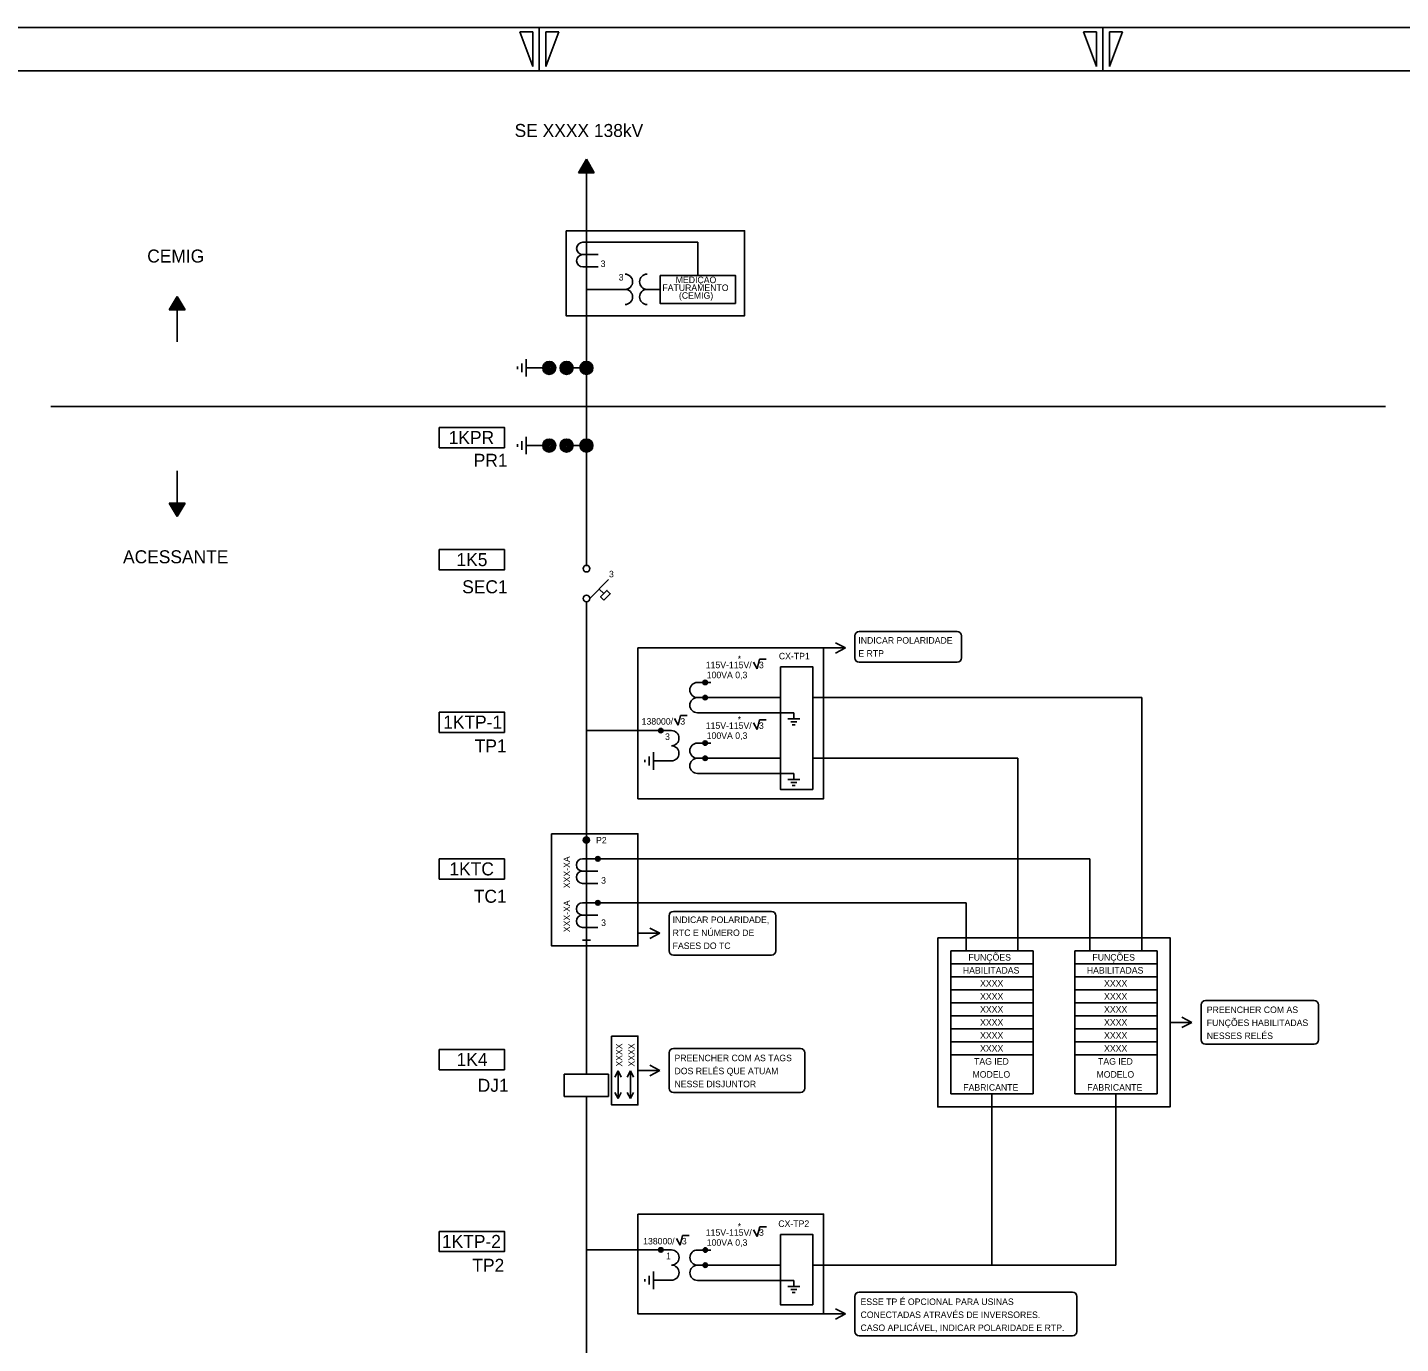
# Model space of a CAD drawing. Extents: x 563 to 1404, y 358 to 952.
# Drawn here: x 785.5 to 1102.2, y 648.4 to 952 of the extents above; entities that cross this region are included whole.
import ezdxf

# ---------------------------------------------------------------- set-up
doc = ezdxf.new("R2010")
doc.units = 0
doc.layers.add('New Level (0)', color=7, linetype='Continuous')

# ---------------------------------------------------------------- blocks, each defined once
blk = doc.blocks.new('_U3')
for p, q in [((-1.47, 0.42), (-0.62, -1.12)), ((-0.62, -1.12), (-0.07, 1.12)), ((-0.07, 1.12), (1.47, 1.12))]:
    blk.add_line(p, q)

msp = doc.modelspace()

# ---------------------------------------------------------------- linework, layer by layer
for p, q in [((914.46, 921.55), (912.65, 918.45)), ((914.46, 921.34), (912.83, 918.55)), ((912.83, 918.55), (916.08, 918.55)), ((914.46, 921.14), (913.01, 918.66)), ((913.01, 918.66), (915.9, 918.66)), ((914.46, 920.93), (913.19, 918.76)), ((913.19, 918.76), (915.72, 918.76)), ((914.46, 920.72), (913.37, 918.86)), ((913.37, 918.86), (915.54, 918.86)), ((914.46, 920.52), (913.55, 918.97)), ((913.55, 918.97), (915.36, 918.97)), ((914.46, 920.31), (913.73, 919.07)), ((913.73, 919.07), (915.18, 919.07)), ((914.46, 920.1), (913.91, 919.17)), ((913.91, 919.17), (915, 919.17)), ((914.46, 919.9), (914.09, 919.28)), ((914.09, 919.28), (914.82, 919.28)), ((914.46, 919.69), (914.27, 919.38)), ((914.27, 919.38), (914.64, 919.38)), ((916.27, 918.45), (914.46, 921.55)), ((916.08, 918.55), (914.46, 921.34)), ((915.9, 918.66), (914.46, 921.14)), ((915.72, 918.76), (914.46, 920.93)), ((915.54, 918.86), (914.46, 920.72)), ((915.36, 918.97), (914.46, 920.52)), ((915.18, 919.07), (914.46, 920.31)), ((915, 919.17), (914.46, 920.1)), ((914.82, 919.28), (914.46, 919.9)), ((914.64, 919.38), (914.46, 919.69)), ((912.65, 918.45), (916.27, 918.45)), ((912.65, 918.45), (916.27, 918.45)), ((914.46, 827.91), (914.46, 918.45)), ((913.61, 902.41), (917.15, 902.41)), ((913.61, 899.58), (917.15, 899.58)), ((917.15, 902.41), (940.14, 902.41)), ((913.61, 896.75), (917.15, 896.75)), ((914.52, 891.56), (923.36, 891.56)), ((928.46, 891.56), (931.46, 891.56)), ((820.05, 889.94), (818.24, 886.84)), ((820.05, 889.73), (818.42, 886.94)), ((818.42, 886.94), (821.67, 886.94)), ((820.05, 889.53), (818.6, 887.05)), ((818.6, 887.05), (821.49, 887.05)), ((820.05, 889.32), (818.78, 887.15)), ((818.78, 887.15), (821.31, 887.15)), ((820.05, 889.11), (818.96, 887.25)), ((818.96, 887.25), (821.13, 887.25)), ((820.05, 888.91), (819.14, 887.36)), ((819.14, 887.36), (820.95, 887.36)), ((820.05, 888.7), (819.32, 887.46)), ((819.32, 887.46), (820.77, 887.46)), ((820.05, 888.49), (819.5, 887.56)), ((819.5, 887.56), (820.59, 887.56)), ((820.05, 888.29), (819.68, 887.67)), ((819.68, 887.67), (820.41, 887.67)), ((820.05, 888.08), (819.86, 887.77)), ((819.86, 887.77), (820.23, 887.77)), ((821.86, 886.84), (820.05, 889.94)), ((821.67, 886.94), (820.05, 889.73)), ((821.49, 887.05), (820.05, 889.53)), ((821.31, 887.15), (820.05, 889.32)), ((821.13, 887.25), (820.05, 889.11)), ((820.95, 887.36), (820.05, 888.91)), ((820.77, 887.46), (820.05, 888.7)), ((820.59, 887.56), (820.05, 888.49)), ((820.41, 887.67), (820.05, 888.29)), ((820.23, 887.77), (820.05, 888.08)), ((818.24, 886.84), (821.86, 886.84)), ((818.24, 886.84), (821.86, 886.84)), ((820.05, 879.42), (820.05, 886.84)), ((899.55, 874.43), (899.55, 872.43)), ((900.55, 871.43), (900.55, 875.43)), ((898.55, 873.73), (898.55, 873.13)), ((898.55, 873.43), (898.55, 873.43)), ((901.87, 873.43), (900.55, 873.43)), ((905.87, 873.43), (901.87, 873.43)), ((914.46, 873.43), (909.87, 873.43)), ((1098.74, 864.56), (790.91, 864.56)), ((898.55, 855.83), (898.55, 855.23)), ((898.55, 855.53), (898.55, 855.53)), ((899.55, 856.53), (899.55, 854.53)), ((900.55, 853.53), (900.55, 857.53)), ((901.87, 855.53), (900.55, 855.53)), ((905.87, 855.53), (901.87, 855.53)), ((914.46, 855.53), (909.87, 855.53)), ((820.05, 849.69), (820.05, 842.28)), ((821.86, 842.28), (818.24, 842.28)), ((818.24, 842.28), (820.05, 839.18)), ((821.86, 842.28), (818.24, 842.28)), ((821.67, 842.18), (818.42, 842.18)), ((818.42, 842.18), (820.05, 839.39)), ((821.49, 842.07), (818.6, 842.07)), ((818.6, 842.07), (820.05, 839.59)), ((821.31, 841.97), (818.78, 841.97)), ((818.78, 841.97), (820.05, 839.8)), ((821.13, 841.87), (818.96, 841.87)), ((818.96, 841.87), (820.05, 840.01)), ((820.95, 841.76), (819.14, 841.76)), ((819.14, 841.76), (820.05, 840.21)), ((820.77, 841.66), (819.32, 841.66)), ((819.32, 841.66), (820.05, 840.42)), ((820.59, 841.56), (819.5, 841.56)), ((819.5, 841.56), (820.05, 840.63)), ((820.41, 841.45), (819.68, 841.45)), ((819.68, 841.45), (820.05, 840.83)), ((820.23, 841.35), (819.86, 841.35)), ((819.86, 841.35), (820.05, 841.04)), ((820.05, 839.18), (821.86, 842.28)), ((820.05, 839.39), (821.67, 842.18)), ((820.05, 839.59), (821.49, 842.07)), ((820.05, 839.8), (821.31, 841.97)), ((820.05, 840.01), (821.13, 841.87)), ((820.05, 840.21), (820.95, 841.76)), ((820.05, 840.42), (820.77, 841.66)), ((820.05, 840.63), (820.59, 841.56)), ((820.05, 840.83), (820.41, 841.45)), ((820.05, 841.04), (820.23, 841.35)), ((919.56, 824.61), (915.22, 820.27)), ((918.45, 821.38), (917.39, 822.44)), ((914.46, 819.5), (914.46, 710.55)), ((940.05, 800.9), (943.16, 800.9)), ((940.05, 797.4), (959.19, 797.4)), ((966.67, 797.4), (1042.59, 797.4)), ((1042.59, 797.4), (1042.59, 739)), ((940.05, 793.9), (962.28, 793.9)), ((963.68, 792.5), (960.88, 792.5)), ((962.28, 793.9), (962.28, 792.5)), ((914.46, 789.8), (934.05, 789.8)), ((961.58, 791.8), (962.98, 791.8)), ((961.94, 791.1), (962.62, 791.1)), ((940.05, 786.91), (943.16, 786.91)), ((927.92, 783.04), (927.92, 782.5)), ((928.93, 781.78), (928.93, 783.82)), ((929.96, 784.85), (929.96, 780.75)), ((934.05, 782.8), (929.96, 782.8)), ((940.05, 783.41), (943.16, 783.41)), ((940.05, 783.41), (959.19, 783.41)), ((966.67, 783.41), (1013.99, 783.41)), ((1013.99, 783.41), (1013.99, 739)), ((940.05, 779.91), (962.28, 779.91)), ((962.28, 779.91), (962.28, 778.51)), ((963.68, 778.51), (960.88, 778.51)), ((961.58, 777.81), (962.98, 777.81)), ((961.94, 777.11), (962.62, 777.11)), ((913.55, 760.21), (1030.61, 760.21)), ((1030.61, 760.21), (1030.61, 739)), ((913.55, 757.38), (917.09, 757.38)), ((913.55, 754.55), (917.09, 754.55)), ((913.55, 750.07), (1002.01, 750.07)), ((1002.01, 750.07), (1002.01, 739)), ((913.55, 747.24), (917.09, 747.24)), ((913.55, 744.41), (917.09, 744.41)), ((1017.49, 739), (998.51, 739)), ((998.51, 739), (998.51, 706)), ((1017.49, 739), (1017.49, 706)), ((1046.09, 739), (1027.11, 739)), ((1027.11, 739), (1027.11, 706)), ((1046.09, 739), (1046.09, 706)), ((1017.49, 736), (998.51, 736)), ((1046.09, 736), (1027.11, 736)), ((1017.49, 733), (998.51, 733)), ((1046.09, 733), (1027.11, 733)), ((1017.49, 730), (998.51, 730)), ((1046.09, 730), (1027.11, 730)), ((1017.49, 727), (998.51, 727)), ((1046.09, 727), (1027.11, 727)), ((1017.49, 724), (998.51, 724)), ((1046.09, 724), (1027.11, 724)), ((1017.49, 721), (998.51, 721)), ((1017.49, 721), (998.51, 721)), ((1046.09, 721), (1027.11, 721)), ((1046.09, 721), (1027.11, 721)), ((1017.49, 718), (998.51, 718)), ((1046.09, 718), (1027.11, 718)), ((1017.49, 715), (998.51, 715)), ((1046.09, 715), (1027.11, 715)), ((909.34, 705.43), (909.34, 710.55)), ((909.34, 710.55), (919.58, 710.55)), ((919.58, 710.55), (919.58, 705.43)), ((921.74, 711.3), (921.03, 709.89)), ((921.74, 704.93), (921.74, 711.3)), ((921.74, 711.3), (922.44, 709.89)), ((924.59, 711.3), (923.88, 709.89)), ((924.59, 704.93), (924.59, 711.3)), ((924.59, 711.3), (925.29, 709.89)), ((921.74, 704.93), (921.03, 706.35)), ((921.74, 704.93), (922.44, 706.35)), ((924.59, 704.93), (923.88, 706.35)), ((924.59, 704.93), (925.29, 706.35)), ((919.58, 705.43), (909.34, 705.43)), ((914.46, 705.43), (914.46, 637.7)), ((1017.49, 706), (998.51, 706)), ((1008, 706), (1008, 666.5)), ((1046.09, 706), (1027.11, 706)), ((1036.6, 706), (1036.6, 666.5)), ((914.46, 670.03), (934.06, 670.03)), ((940.06, 670), (943.17, 670)), ((940.06, 666.5), (959.19, 666.5)), ((966.67, 666.5), (1036.6, 666.5)), ((927.93, 663.27), (927.93, 662.73)), ((928.94, 662.01), (928.94, 664.05)), ((929.96, 665.08), (929.96, 660.98)), ((934.06, 663.03), (929.96, 663.03)), ((940.06, 663), (962.29, 663)), ((962.29, 663), (962.29, 661.6)), ((963.69, 661.6), (960.89, 661.6)), ((961.59, 660.9), (962.99, 660.9)), ((961.94, 660.2), (962.63, 660.2))]:
    msp.add_line(p, q)
msp.add_lwpolyline([(918.48, 819.88), (917.72, 820.64), (919.19, 822.12), (919.96, 821.35)], close=True)
for centre, radius in [((905.87, 873.43), 1.5), ((905.87, 873.43), 1.25), ((905.87, 873.43), 1), ((905.87, 873.43), 0.75), ((909.87, 873.43), 1.5), ((909.87, 873.43), 1.25), ((909.87, 873.43), 1), ((909.87, 873.43), 0.75), ((914.46, 873.43), 1.5), ((914.46, 873.43), 1.25), ((914.46, 873.43), 1), ((914.46, 873.43), 0.75), ((905.87, 873.43), 0.5), ((905.87, 873.43), 0.25), ((909.87, 873.43), 0.5), ((909.87, 873.43), 0.25), ((914.46, 873.43), 0.5), ((914.46, 873.43), 0.25), ((905.87, 855.53), 1.5), ((905.87, 855.53), 1.25), ((905.87, 855.53), 1), ((905.87, 855.53), 0.75), ((905.87, 855.53), 0.5), ((905.87, 855.53), 0.25), ((909.87, 855.53), 1.5), ((909.87, 855.53), 1.25), ((909.87, 855.53), 1), ((909.87, 855.53), 0.75), ((909.87, 855.53), 0.5), ((909.87, 855.53), 0.25), ((914.46, 855.53), 1.5), ((914.46, 855.53), 1.25), ((914.46, 855.53), 1), ((914.46, 855.53), 0.75), ((914.46, 855.53), 0.5), ((914.46, 855.53), 0.25), ((914.46, 827.14), 0.768), ((914.46, 820.27), 0.768), ((941.85, 800.9), 0.511), ((941.85, 800.9), 0.288), ((941.85, 797.4), 0.511), ((941.85, 797.4), 0.288), ((931.61, 789.8), 0.511), ((931.61, 789.8), 0.288), ((941.85, 786.91), 0.511), ((941.85, 786.91), 0.288), ((941.85, 783.41), 0.511), ((941.85, 783.41), 0.288), ((914.45, 764.55), 0.729), ((914.46, 764.54), 0.511), ((914.46, 764.54), 0.288), ((917.09, 760.21), 0.511), ((917.09, 760.21), 0.288), ((917.09, 750.07), 0.511), ((917.09, 750.07), 0.288), ((931.62, 670.03), 0.511), ((931.62, 670.03), 0.288), ((941.86, 670), 0.511), ((941.86, 670), 0.288), ((941.86, 666.5), 0.511), ((941.86, 666.5), 0.288)]:
    msp.add_circle(centre, radius)
for centre, radius, start, end in [((913.61, 900.99), 1.42, 90, 270), ((913.61, 898.16), 1.42, 90, 270), ((923.36, 893.31), 1.75, 270, 90), ((928.46, 893.31), 1.75, 90, 270), ((923.36, 889.81), 1.75, 270, 90), ((928.46, 889.81), 1.75, 90, 270), ((940.05, 799.15), 1.75, 90, 270), ((940.05, 795.65), 1.75, 90, 270), ((934.05, 788.05), 1.75, 270, 90), ((934.05, 784.55), 1.75, 270, 90), ((940.05, 785.16), 1.75, 90, 270), ((940.05, 781.66), 1.75, 90, 270), ((913.55, 758.8), 1.42, 90, 270), ((913.55, 755.97), 1.42, 90, 270), ((913.55, 748.66), 1.42, 90, 270), ((913.55, 745.83), 1.42, 90, 270), ((934.06, 668.28), 1.75, 270, 90), ((940.06, 668.25), 1.75, 90, 270), ((934.06, 664.78), 1.75, 270, 90), ((940.06, 664.75), 1.75, 90, 270)]:
    msp.add_arc(centre, radius, start, end)
at = {"layer": 'New Level (0)'}
for p, q in [((1403.58, 951.96), (562.58, 951.96)), ((1403.58, 951.96), (562.58, 951.96)), ((902.08, 950.96), (899.08, 950.96)), ((899.08, 950.96), (902.08, 942.96)), ((902.08, 942.96), (902.08, 950.96)), ((903.58, 951.96), (903.58, 941.96)), ((905.08, 942.96), (905.08, 950.96)), ((905.08, 950.96), (908.08, 950.96)), ((908.08, 950.96), (905.08, 942.96)), ((1032.08, 950.96), (1029.08, 950.96)), ((1029.08, 950.96), (1032.08, 942.96)), ((1032.08, 942.96), (1032.08, 950.96)), ((1033.58, 951.96), (1033.58, 941.96)), ((1035.08, 942.96), (1035.08, 950.96)), ((1035.08, 950.96), (1038.08, 950.96)), ((1038.08, 950.96), (1035.08, 942.96)), ((1393.58, 941.96), (572.58, 941.96)), ((940.14, 894.79), (940.14, 902.41)), ((976.35, 806.55), (976.35, 811.62)), ((977.35, 812.62), (984.7, 812.62)), ((984.7, 812.62), (999.96, 812.62)), ((1000.96, 811.62), (1000.96, 806.55)), ((969.16, 808.86), (974.19, 808.86)), ((974.19, 808.86), (971.89, 810.07)), ((974.19, 808.86), (971.89, 807.65)), ((999.96, 805.55), (977.35, 805.55)), ((934.51, 748.1), (941.86, 748.1)), ((941.86, 748.1), (957.12, 748.1)), ((933.51, 738.99), (933.51, 747.1)), ((958.12, 747.1), (958.12, 738.99)), ((913.56, 741.46), (915.36, 741.46)), ((926.32, 743.04), (931.35, 743.04)), ((931.35, 743.04), (929.05, 744.25)), ((931.35, 743.04), (929.05, 741.83)), ((957.12, 737.99), (934.51, 737.99)), ((1056.28, 718.45), (1056.28, 726.56)), ((1057.28, 727.56), (1064.63, 727.56)), ((1064.63, 727.56), (1082.29, 727.56)), ((1083.29, 726.56), (1083.29, 718.45)), ((1049.09, 722.5), (1054.12, 722.5)), ((1054.12, 722.5), (1051.83, 723.71)), ((1054.12, 722.5), (1051.83, 721.3)), ((934.51, 716.45), (941.86, 716.45)), ((941.86, 716.45), (963.8, 716.45)), ((1082.29, 717.45), (1057.28, 717.45)), ((933.51, 707.33), (933.51, 715.45)), ((964.8, 715.45), (964.8, 707.33)), ((926.32, 711.39), (931.35, 711.39)), ((931.35, 711.39), (929.05, 712.6)), ((931.35, 711.39), (929.05, 710.18)), ((963.8, 706.33), (934.51, 706.33)), ((976.35, 651.19), (976.35, 659.31)), ((977.35, 660.31), (984.71, 660.31)), ((984.71, 660.31), (1026.54, 660.31)), ((1027.54, 659.31), (1027.54, 651.19)), ((974.2, 655.25), (971.9, 656.46)), ((969.17, 655.25), (974.2, 655.25)), ((974.2, 655.25), (971.9, 654.04)), ((1026.54, 650.19), (977.35, 650.19))]:
    msp.add_line(p, q, dxfattribs=at)
for points in [[(909.78, 905.07), (950.94, 905.07), (950.94, 885.46), (909.78, 885.46)], [(931.46, 894.79), (948.81, 894.79), (948.81, 888.32), (931.46, 888.32)], [(880.5, 859.7), (895.52, 859.7), (895.52, 855.02), (880.5, 855.02)], [(880.5, 831.54), (895.52, 831.54), (895.52, 826.86), (880.5, 826.86)], [(926.32, 808.86), (969.16, 808.86), (969.16, 774.07), (926.32, 774.07)], [(959.19, 804.5), (966.67, 804.5), (966.67, 776.21), (959.19, 776.21)], [(880.5, 794.07), (895.52, 794.07), (895.52, 789.39), (880.5, 789.39)], [(906.42, 766.02), (926.32, 766.02), (926.32, 740.12), (906.42, 740.12)], [(880.5, 760.21), (895.52, 760.21), (895.52, 755.53), (880.5, 755.53)], [(995.51, 742), (1049.09, 742), (1049.09, 703), (995.51, 703)], [(920.25, 719.33), (926.32, 719.33), (926.32, 703.45), (920.25, 703.45)], [(880.5, 716.26), (895.52, 716.26), (895.52, 711.58), (880.5, 711.58)], [(926.33, 678.3), (969.17, 678.3), (969.17, 655.25), (926.33, 655.25)], [(880.5, 674.3), (895.52, 674.3), (895.52, 669.62), (880.5, 669.62)], [(959.19, 673.6), (966.67, 673.6), (966.67, 657.39), (959.19, 657.39)]]:
    msp.add_lwpolyline(points, close=True, dxfattribs=at)
for centre, start, end in [((977.35, 811.62), 90, 180), ((999.96, 811.62), 0, 90), ((977.35, 806.55), 180, 270), ((999.96, 806.55), 270, 0), ((934.51, 747.1), 90, 180), ((957.12, 747.1), 0, 90), ((934.51, 738.99), 180, 270), ((957.12, 738.99), 270, 0), ((1057.28, 726.56), 90, 180), ((1082.29, 726.56), 0, 90), ((934.51, 715.45), 90, 180), ((963.8, 715.45), 0, 90), ((1057.28, 718.45), 180, 270), ((1082.29, 718.45), 270, 0), ((934.51, 707.33), 180, 270), ((963.8, 707.33), 270, 0), ((977.35, 659.31), 90, 180), ((1026.54, 659.31), 0, 90), ((977.35, 651.19), 180, 270), ((1026.54, 651.19), 270, 0)]:
    msp.add_arc(centre, 1, start, end, dxfattribs=at)

# ---------------------------------------------------------------- block references
for p in [(954.48, 805.15), (936.25, 792.13), (954.48, 791.16), (954.49, 674.25), (936.7, 672.26)]:
    msp.add_blockref('_U3', p)

# ---------------------------------------------------------------- texts
for s, height, p in [('SE XXXX 138kV', 3, (897.89, 926.7)), ('CEMIG', 3, (813.14, 897.74)), ('3', 1.5, (917.73, 896.71)), ('3', 1.5, (921.9, 893.6)), ('MEDIÇÃO', 1.5, (935.05, 892.99)), ('FATURAMENTO', 1.5, (931.97, 891.19)), ('(CEMIG)', 1.5, (935.79, 889.39)), ('1KPR', 3, (882.68, 855.88)), ('PR1', 3, (888.46, 850.63)), ('ACESSANTE', 3, (807.56, 828.38)), ('1K5', 3, (884.48, 827.72)), ('3', 1.5, (919.65, 825.14)), ('SEC1', 3, (885.8, 821.46)), ('INDICAR POLARIDADE ', 1.5, (977.18, 809.85)), ('CX-TP1', 1.5, (958.84, 806.23)), ('E RTP ', 1.5, (977.18, 806.85)), ('115V-115V/   3', 1.5, (941.98, 804.18)), ('*', 1.5, (949.34, 805.6)), ('100VA 0,3', 1.5, (942.2, 801.87)), ('1KTP-1', 3, (881.41, 790.25)), ('138000/   3', 1.5, (927.19, 791.17)), ('*', 1.5, (949.34, 791.62)), ('3', 1.5, (932.59, 787.65)), ('115V-115V/   3', 1.5, (941.98, 790.19)), ('100VA 0,3', 1.5, (942.2, 787.88)), ('TP1', 3, (888.69, 784.75)), ('P2', 1.5, (916.67, 763.77)), ('1KTC', 3, (882.85, 756.4)), ('3', 1.5, (917.84, 754.49)), ('TC1', 3, (888.47, 750.08)), ('3', 1.5, (917.84, 744.74)), ('INDICAR POLARIDADE, ', 1.5, (934.34, 745.42)), ('RTC E NÚMERO DE ', 1.5, (934.34, 742.42)), ('FASES DO TC', 1.5, (934.34, 739.42)), ('FUNÇÕES ', 1.5, (1002.57, 736.75)), ('FUNÇÕES ', 1.5, (1031.17, 736.75)), ('HABILITADAS', 1.5, (1001.28, 733.75)), ('HABILITADAS', 1.5, (1029.88, 733.75)), ('XXXX', 1.5, (1005.26, 730.75)), ('XXXX', 1.5, (1033.86, 730.75)), ('XXXX', 1.5, (1005.26, 727.75)), ('XXXX', 1.5, (1033.86, 727.75)), ('XXXX', 1.5, (1005.26, 724.75)), ('XXXX', 1.5, (1033.86, 724.75)), ('PREENCHER COM AS ', 1.5, (1057.55, 724.66)), ('XXXX', 1.5, (1005.26, 721.75)), ('XXXX', 1.5, (1033.86, 721.75)), ('FUNÇÕES HABILITADAS ', 1.5, (1057.55, 721.66)), ('XXXX', 1.5, (1005.26, 718.75)), ('XXXX', 1.5, (1033.86, 718.75)), ('NESSES RELÉS', 1.5, (1057.55, 718.66)), ('XXXX', 1.5, (1005.26, 715.75)), ('XXXX', 1.5, (1033.86, 715.75)), ('1K4', 3, (884.5, 712.44)), ('PREENCHER COM AS TAGS ', 1.5, (934.77, 713.54)), ('TAG IED', 1.5, (1003.87, 712.75)), ('TAG IED', 1.5, (1032.47, 712.75)), ('DJ1', 3, (889.38, 706.49)), ('DOS RELÉS QUE ATUAM ', 1.5, (934.77, 710.54)), ('MODELO', 1.5, (1003.51, 709.75)), ('MODELO', 1.5, (1032.11, 709.75)), ('NESSE DISJUNTOR', 1.5, (934.77, 707.54)), ('FABRICANTE', 1.5, (1001.38, 706.75)), ('FABRICANTE', 1.5, (1029.98, 706.75)), ('115V-115V/   3', 1.5, (941.99, 673.28)), ('*', 1.5, (949.35, 674.7)), ('CX-TP2', 1.5, (958.71, 675.33)), ('1KTP-2', 3, (881.13, 670.48)), ('138000/   3', 1.5, (927.54, 671.29)), ('100VA 0,3', 1.5, (942.21, 670.97)), ('1', 1.5, (932.81, 667.87)), ('TP2', 3, (888.14, 664.98)), ('ESSE TP É OPCIONAL PARA USINAS ', 1.5, (977.68, 657.32)), ('CONECTADAS ATRAVÉS DE INVERSORES.', 1.5, (977.68, 654.32)), ('CASO APLICÁVEL, INDICAR POLARIDADE E RTP.', 1.5, (977.68, 651.32))]:
    msp.add_text(s, height=height).set_placement(p)
for s, p in [('XXX-XA', (910.68, 753.44)), ('XXX-XA', (910.68, 743.3)), ('XXXX', (922.74, 712.3)), ('XXXX', (925.59, 712.3))]:
    msp.add_text(s, height=1.5, rotation=90).set_placement(p)

doc.saveas('drawing.dxf')
